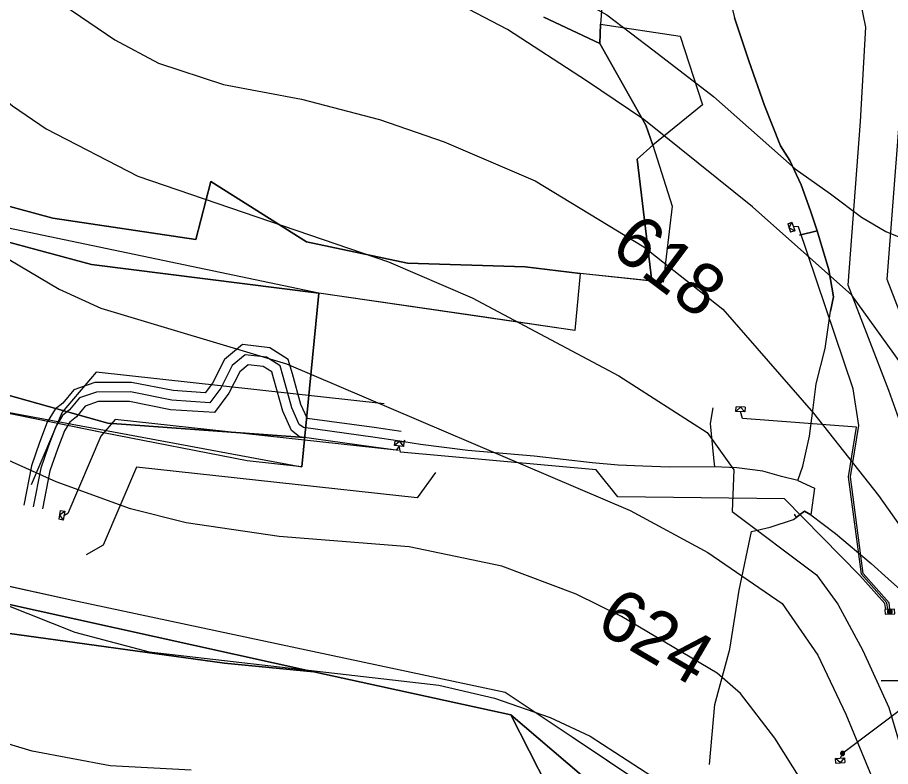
# Model space of a CAD drawing. Extents: x -709418 to -703832, y -1161719 to -1157826.
# Drawn here: x -707168.1 to -707032.1, y -1160311.5 to -1160194.8 of the extents above; entities that cross this region are included whole.
import ezdxf

# ---------------------------------------------------------------- set-up
doc = ezdxf.new("R2010")
doc.units = 0
for name, color, linetype in [('102_obvod PÚ', 7, 'Continuous'), ('106_zastavitelné plochy', 7, 'Continuous'), ('120_vrstevnice hlavní', 7, 'Continuous'), ('121_vrstevnice hlavní_popis', 7, 'Continuous'), ('122_vrstevnice základní', 7, 'Continuous'), ('204_zahrada_KN', 7, 'Continuous'), ('206_TTP_KN', 7, 'Continuous'), ('210_ostatní plocha_KN', 7, 'Continuous'), ('501_vodní tok', 7, 'Continuous'), ('708_el NN nadzemní a podzemní_ E.ON', 7, 'Continuous'), ('717_elektronická komunikace O2', 7, 'Continuous'), ('735_OP sítí TI', 7, 'Continuous')]:
    doc.layers.add(name, color=color, linetype=linetype)

# ---------------------------------------------------------------- blocks, each defined once
blk = doc.blocks.new('Elektro - Implicitní$0$NN4601')
for points in [[(0.63, 0), (0.62, 0.07), (0.61, 0.13), (0.6, 0.2), (0.57, 0.26), (0.54, 0.32), (0.51, 0.37), (0.47, 0.42), (0.42, 0.47), (0.37, 0.51), (0.31, 0.55), (0.25, 0.58), (0.19, 0.6), (0.13, 0.62), (0.06, 0.63), (0, 0.63), (-0.07, 0.63), (-0.13, 0.62), (-0.2, 0.6), (-0.26, 0.58), (-0.32, 0.55), (-0.37, 0.51), (-0.42, 0.47), (-0.47, 0.42), (-0.51, 0.37), (-0.55, 0.32), (-0.58, 0.26), (-0.6, 0.2), (-0.62, 0.13), (-0.63, 0.07), (-0.63, 0), (-0.63, -0.07), (-0.62, -0.13), (-0.6, -0.19), (-0.58, -0.26), (-0.55, -0.31), (-0.51, -0.37), (-0.47, -0.42), (-0.42, -0.47), (-0.37, -0.51), (-0.32, -0.54), (-0.26, -0.57), (-0.2, -0.6), (-0.13, -0.62), (-0.07, -0.63), (0, -0.63), (0.06, -0.63), (0.13, -0.62), (0.19, -0.6), (0.25, -0.57), (0.31, -0.54), (0.37, -0.51), (0.42, -0.47), (0.47, -0.42), (0.51, -0.37), (0.54, -0.31), (0.57, -0.26), (0.6, -0.19), (0.61, -0.13), (0.62, -0.07), (0.63, 0)], [(0.47, 0), (0.47, 0.05), (0.46, 0.1), (0.45, 0.15), (0.43, 0.19), (0.41, 0.24), (0.38, 0.28), (0.35, 0.32), (0.31, 0.35), (0.28, 0.38), (0.23, 0.41), (0.19, 0.43), (0.14, 0.45), (0.1, 0.46), (0.05, 0.47), (0, 0.47), (-0.05, 0.47), (-0.1, 0.46), (-0.15, 0.45), (-0.19, 0.43), (-0.24, 0.41), (-0.28, 0.38), (-0.32, 0.35), (-0.35, 0.32), (-0.38, 0.28), (-0.41, 0.24), (-0.43, 0.19), (-0.45, 0.15), (-0.46, 0.1), (-0.47, 0.05), (-0.47, 0), (-0.47, -0.05), (-0.46, -0.1), (-0.45, -0.15), (-0.43, -0.19), (-0.41, -0.24), (-0.38, -0.28), (-0.35, -0.32), (-0.32, -0.35), (-0.28, -0.38), (-0.24, -0.41), (-0.19, -0.43), (-0.15, -0.45), (-0.1, -0.46), (-0.05, -0.47), (0, -0.47), (0.05, -0.47), (0.1, -0.46), (0.14, -0.45), (0.19, -0.43), (0.23, -0.41), (0.28, -0.38), (0.31, -0.35), (0.35, -0.32), (0.38, -0.28), (0.41, -0.24), (0.43, -0.19), (0.45, -0.15), (0.46, -0.1), (0.47, -0.05), (0.47, 0)], [(0.31, 0), (0.31, 0.03), (0.31, 0.07), (0.3, 0.1), (0.29, 0.13), (0.27, 0.16), (0.25, 0.19), (0.23, 0.21), (0.21, 0.23), (0.18, 0.26), (0.15, 0.27), (0.13, 0.29), (0.09, 0.3), (0.06, 0.31), (0.03, 0.31), (0, 0.32), (-0.04, 0.31), (-0.07, 0.31), (-0.1, 0.3), (-0.13, 0.29), (-0.16, 0.27), (-0.19, 0.26), (-0.21, 0.23), (-0.24, 0.21), (-0.26, 0.19), (-0.28, 0.16), (-0.29, 0.13), (-0.3, 0.1), (-0.31, 0.07), (-0.32, 0.03), (-0.32, 0), (-0.32, -0.03), (-0.31, -0.06), (-0.3, -0.1), (-0.29, -0.13), (-0.28, -0.16), (-0.26, -0.18), (-0.24, -0.21), (-0.21, -0.23), (-0.19, -0.25), (-0.16, -0.27), (-0.13, -0.29), (-0.1, -0.3), (-0.07, -0.31), (-0.04, -0.31), (0, -0.31), (0.03, -0.31), (0.06, -0.31), (0.09, -0.3), (0.13, -0.29), (0.15, -0.27), (0.18, -0.25), (0.21, -0.23), (0.23, -0.21), (0.25, -0.18), (0.27, -0.16), (0.29, -0.13), (0.3, -0.1), (0.31, -0.06), (0.31, -0.03), (0.31, 0)], [(0.15, 0), (0.15, 0.02), (0.15, 0.03), (0.15, 0.05), (0.14, 0.06), (0.13, 0.08), (0.13, 0.09), (0.11, 0.11), (0.1, 0.12), (0.09, 0.13), (0.08, 0.14), (0.06, 0.14), (0.05, 0.15), (0.03, 0.15), (0.01, 0.16), (0, 0.16), (-0.02, 0.16), (-0.04, 0.15), (-0.05, 0.15), (-0.07, 0.14), (-0.08, 0.14), (-0.09, 0.13), (-0.11, 0.12), (-0.12, 0.11), (-0.13, 0.09), (-0.14, 0.08), (-0.15, 0.06), (-0.15, 0.05), (-0.16, 0.03), (-0.16, 0.02), (-0.16, 0), (-0.16, -0.02), (-0.16, -0.03), (-0.15, -0.05), (-0.15, -0.06), (-0.14, -0.08), (-0.13, -0.09), (-0.12, -0.1), (-0.11, -0.12), (-0.09, -0.13), (-0.08, -0.14), (-0.07, -0.14), (-0.05, -0.15), (-0.04, -0.15), (-0.02, -0.16), (0, -0.16), (0.01, -0.16), (0.03, -0.15), (0.05, -0.15), (0.06, -0.14), (0.08, -0.14), (0.09, -0.13), (0.1, -0.12), (0.11, -0.1), (0.13, -0.09), (0.13, -0.08), (0.14, -0.06), (0.15, -0.05), (0.15, -0.03), (0.15, -0.02), (0.15, 0)]]:
    blk.add_lwpolyline(points)
blk = doc.blocks.new('Elektro - Implicitní$0$NN6301')
for points in [[(0, -0.7), (-0.7, 0)], [(-0.7, -0.7), (-0.7, 0), (0.7, 0), (0.7, -0.7)], [(-0.7, -0.7), (0.7, -0.7)], [(0, -0.7), (0.7, 0)]]:
    blk.add_lwpolyline(points)
blk = doc.blocks.new('Elektro - Implicitní$0$NN6201')
for points in [[(0.75, 0), (-0.75, 0)], [(-0.75, 0), (-0.75, -0.75)], [(0.75, -0.75), (0.75, 0)], [(-0.75, -0.75), (0.75, -0.75)], [(0.37, -0.18), (-0.38, -0.18)], [(-0.38, -0.18), (-0.38, -0.56)], [(-0.38, -0.56), (0.37, -0.56)], [(0.32, -0.23), (-0.33, -0.23)], [(-0.33, -0.23), (-0.33, -0.51)], [(-0.33, -0.51), (0.32, -0.51)], [(0.27, -0.27), (-0.28, -0.27)], [(-0.28, -0.27), (-0.28, -0.46)], [(-0.28, -0.46), (0.27, -0.46)], [(0.23, -0.32), (-0.23, -0.32)], [(-0.23, -0.32), (-0.23, -0.42)], [(-0.23, -0.42), (0.23, -0.42)], [(-0.19, -0.37), (0.19, -0.37)], [(0.23, -0.42), (0.23, -0.32)], [(0.27, -0.46), (0.27, -0.27)], [(0.32, -0.51), (0.32, -0.23)], [(0.37, -0.56), (0.37, -0.18)]]:
    blk.add_lwpolyline(points)

msp = doc.modelspace()

# ---------------------------------------------------------------- linework, layer by layer
at = {"layer": '102_obvod PÚ'}
for points in [[(-707069.74, -1160077.73), (-707051.26, -1160126.04), (-707048.48, -1160146.16), (-707064.34, -1160162.06), (-707070.51, -1160163.59), (-707070.58, -1160162.59), (-707113.49, -1160155.37), (-707117.48, -1160184.48), (-707076.81, -1160189.76), (-707077.24, -1160195.83), (-707064.82, -1160197.68), (-707061.39, -1160208.39), (-707069.1, -1160214.67), (-707066.07, -1160224.17), (-707067.49, -1160236.02), (-707080.41, -1160234.66), (-707081.27, -1160243.51), (-707121.16, -1160237.73), (-707123.8, -1160264.78), (-707132.29, -1160263.85), (-707154.7, -1160259.5), (-707179.46, -1160254.43)], [(-707185.1, -1160279.91), (-707159.48, -1160285.54), (-707092.11, -1160299.89), (-707081.66, -1160306.81), (-707065.6, -1160317.58)]]:
    msp.add_lwpolyline(points, dxfattribs=at)
at = {"layer": '106_zastavitelné plochy'}
msp.add_lwpolyline([(-707218.12, -1160217.44), (-707231.07, -1160267.18), (-707185.1, -1160279.91), (-707179.46, -1160254.43), (-707123.8, -1160264.78), (-707121.16, -1160237.73), (-707218.12, -1160217.44)], dxfattribs=at)
at = {"layer": '120_vrstevnice hlavní'}
msp.add_lwpolyline([(-707200.36, -1160178.58), (-707183.6, -1160196.23), (-707168.85, -1160208.52), (-707163.64, -1160212.14), (-707149.32, -1160219.52), (-707110.26, -1160232.82), (-707097.25, -1160238.46), (-707074.39, -1160250.61), (-707060.65, -1160259.44), (-707056.47, -1160265.22), (-707056.72, -1160271.75), (-707043.58, -1160281.57), (-707040.29, -1160286.17), (-707036.39, -1160293.38), (-707032.35, -1160302.26), (-707030.28, -1160309.28)], dxfattribs=at)
at = {"layer": '122_vrstevnice základní'}
for points in [[(-707228.15, -1160106.11), (-707204.14, -1160119.57), (-707193.87, -1160126.8), (-707180.27, -1160138.95), (-707162.62, -1160151.24), (-707144.11, -1160162.96), (-707136.44, -1160167.15), (-707127.91, -1160170.92), (-707107.95, -1160177.57), (-707101.73, -1160180.17), (-707076.27, -1160194.35), (-707068.9, -1160199.99), (-707059.64, -1160207.08), (-707046.91, -1160218.36), (-707041.41, -1160222.26), (-707036.62, -1160225.88), (-707032.82, -1160228.1), (-707029, -1160229.65)], [(-707171.93, -1160185.32), (-707152.93, -1160198.25), (-707146.14, -1160201.87), (-707136.01, -1160205.2), (-707123.86, -1160207.51), (-707111.71, -1160210.69), (-707101.59, -1160214.16), (-707087.41, -1160220.24), (-707070.49, -1160230.51), (-707058.19, -1160240.2), (-707044.08, -1160256.43), (-707033.93, -1160269.23), (-707029.68, -1160275.28), (-707025.1, -1160281.33), (-707020.67, -1160286.06), (-707017.03, -1160287.77), (-707012.11, -1160288.36), (-707005.71, -1160288.09), (-707003.18, -1160285.96), (-707001.47, -1160282.49), (-707001.22, -1160276.33), (-707001.69, -1160264.81), (-706995.49, -1160261.9), (-706993, -1160250.04)], [(-707003.89, -1160225.22), (-707010.68, -1160228.43), (-707010.05, -1160249.05), (-707011.14, -1160255.7), (-707013.03, -1160259.68), (-707016.21, -1160261.14), (-707020.37, -1160260.41), (-707023.5, -1160258.2), (-707025.8, -1160255.17), (-707031.58, -1160247.14), (-707038.09, -1160238.03), (-707053.56, -1160224.29), (-707070.49, -1160210.69), (-707079.45, -1160204.62), (-707091.75, -1160196.66), (-707097.82, -1160193.48), (-707107.95, -1160190.01), (-707122.56, -1160186.39)], [(-707173.89, -1160229.82), (-707161.58, -1160237.08), (-707155.1, -1160240.06), (-707126.17, -1160248.73), (-707072.66, -1160271.59), (-707060.51, -1160278.1), (-707048.93, -1160286.05), (-707043.39, -1160294.11), (-707039.03, -1160303.32), (-707032.8, -1160318.33), (-707030.42, -1160326.35)], [(-707216.25, -1160247.81), (-707208.81, -1160257.2), (-707199.51, -1160265.66), (-707189.82, -1160273.32), (-707182.01, -1160279.11), (-707170, -1160286.2), (-707159.15, -1160290.54), (-707147.58, -1160293.57), (-707102.45, -1160298.78), (-707093.77, -1160300.81), (-707085.1, -1160303.84), (-707078.88, -1160306.74), (-707059.64, -1160319.18), (-707053.71, -1160325.83), (-707046.47, -1160335.67), (-707040.84, -1160347.05), (-707036.98, -1160356.57), (-707033.79, -1160366.42), (-707031, -1160381.41), (-707032.56, -1160386.71), (-707026.38, -1160395.27)], [(-707009.56, -1160420.55), (-707013.67, -1160417.17), (-707015.1, -1160412), (-707016.15, -1160403.5), (-707018.79, -1160390.33), (-707020.84, -1160381.99), (-707021.89, -1160373.85), (-707025.49, -1160344.4), (-707030.48, -1160344.5), (-707033.85, -1160335.48), (-707040, -1160323.09), (-707050.09, -1160307.03), (-707055.44, -1160300.08), (-707059.06, -1160296.9), (-707073.96, -1160288.08), (-707081.05, -1160284.6), (-707092.62, -1160280.27), (-707107.08, -1160277.23), (-707127.33, -1160275.64), (-707141.8, -1160273.47), (-707150.47, -1160271.3), (-707162.05, -1160267.1), (-707173.62, -1160261.9), (-707178.97, -1160258.86)], [(-707141.04, -1160312.04), (-707153.66, -1160311.36), (-707165.81, -1160309.05), (-707186.06, -1160302.98), (-707194.16, -1160299.79), (-707203.12, -1160294.44), (-707212.82, -1160287.21)]]:
    msp.add_lwpolyline(points, dxfattribs=at)
at = {"layer": '204_zahrada_KN'}
for p, q in [((-707211.57, -1160218.56), (-707156.55, -1160233.24)), ((-707156.55, -1160233.24), (-707121.16, -1160237.73)), ((-707121.16, -1160237.73), (-707123.37, -1160260.19)), ((-707154.02, -1160257.98), (-707199.62, -1160245.21)), ((-707123.37, -1160260.19), (-707154.02, -1160257.98))]:
    msp.add_line(p, q, dxfattribs=at)
at = {"layer": '206_TTP_KN'}
for p, q in [((-707086.08, -1160194.71), (-707077.34, -1160198.84)), ((-707077.34, -1160198.84), (-707070.21, -1160211.54)), ((-707070.21, -1160211.54), (-707069.1, -1160214.67)), ((-707069.1, -1160214.67), (-707071.55, -1160216.87)), ((-707071.55, -1160216.87), (-707069.1, -1160214.67)), ((-707069.1, -1160214.67), (-707066.07, -1160224.17)), ((-707071.55, -1160216.87), (-707069.28, -1160235.83)), ((-707069.28, -1160235.83), (-707071.55, -1160216.87)), ((-707137.96, -1160220.33), (-707140.3, -1160229.38)), ((-707123.08, -1160229.75), (-707137.96, -1160220.33)), ((-707162.56, -1160226.02), (-707178.69, -1160221.67)), ((-707066.07, -1160224.17), (-707067.49, -1160236.02)), ((-707140.3, -1160229.38), (-707162.56, -1160226.02)), ((-707107.31, -1160233.07), (-707123.08, -1160229.75)), ((-707089.01, -1160233.6), (-707107.31, -1160233.07)), ((-707080.41, -1160234.66), (-707089.01, -1160233.6)), ((-707069.28, -1160235.83), (-707080.41, -1160234.66)), ((-707067.49, -1160236.02), (-707069.28, -1160235.83)), ((-707181.48, -1160289.09), (-707135.81, -1160295.36)), ((-707135.81, -1160295.36), (-707121.9, -1160296.72)), ((-707121.9, -1160296.72), (-707091.23, -1160303.38)), ((-707091.23, -1160303.38), (-707083.56, -1160318.4)), ((-707083.56, -1160318.4), (-707091.23, -1160303.38)), ((-707091.23, -1160303.38), (-707068.93, -1160322.43))]:
    msp.add_line(p, q, dxfattribs=at)
at = {"layer": '210_ostatní plocha_KN'}
for p, q in [((-707076.81, -1160189.76), (-707077.24, -1160195.83)), ((-707077.34, -1160198.84), (-707086.08, -1160194.71)), ((-707077.24, -1160195.83), (-707077.34, -1160198.84)), ((-707077.34, -1160198.84), (-707077.24, -1160195.83)), ((-707077.24, -1160195.83), (-707064.82, -1160197.68)), ((-707064.82, -1160197.68), (-707061.39, -1160208.39)), ((-707070.21, -1160211.54), (-707077.34, -1160198.84)), ((-707061.39, -1160208.39), (-707069.1, -1160214.67)), ((-707069.1, -1160214.67), (-707070.21, -1160211.54)), ((-707156.55, -1160233.24), (-707211.57, -1160218.56)), ((-707140.3, -1160229.38), (-707137.96, -1160220.33)), ((-707137.96, -1160220.33), (-707123.08, -1160229.75)), ((-707178.69, -1160221.67), (-707162.56, -1160226.02)), ((-707162.56, -1160226.02), (-707140.3, -1160229.38)), ((-707123.08, -1160229.75), (-707107.31, -1160233.07)), ((-707121.16, -1160237.73), (-707156.55, -1160233.24)), ((-707107.31, -1160233.07), (-707089.01, -1160233.6)), ((-707089.01, -1160233.6), (-707080.41, -1160234.66)), ((-707080.41, -1160234.66), (-707081.27, -1160243.51)), ((-707095.62, -1160241.43), (-707121.16, -1160237.73)), ((-707083.04, -1160243.26), (-707095.62, -1160241.43)), ((-707081.27, -1160243.51), (-707083.04, -1160243.26)), ((-707199.62, -1160245.21), (-707154.02, -1160257.98)), ((-707154.7, -1160259.5), (-707179.46, -1160254.43)), ((-707154.02, -1160257.98), (-707123.37, -1160260.19)), ((-707132.29, -1160263.85), (-707154.7, -1160259.5)), ((-707123.37, -1160260.19), (-707123.8, -1160264.78)), ((-707123.8, -1160264.78), (-707132.29, -1160263.85)), ((-707121.9, -1160296.72), (-707204.36, -1160278.47)), ((-707204.36, -1160278.47), (-707121.9, -1160296.72)), ((-707185.1, -1160279.91), (-707159.48, -1160285.54)), ((-707159.48, -1160285.54), (-707092.11, -1160299.89)), ((-707135.81, -1160295.36), (-707181.48, -1160289.09)), ((-707121.9, -1160296.72), (-707135.81, -1160295.36)), ((-707091.23, -1160303.38), (-707121.9, -1160296.72)), ((-707092.11, -1160299.89), (-707081.66, -1160306.81)), ((-707068.93, -1160322.43), (-707091.23, -1160303.38)), ((-707081.66, -1160306.81), (-707065.6, -1160317.58))]:
    msp.add_line(p, q, dxfattribs=at)
at = {"layer": '501_vodní tok'}
msp.add_lwpolyline([(-707026.72, -1160250.76), (-707032.59, -1160235.58), (-707030.74, -1160211.37)], dxfattribs=at)
at = {"layer": '708_el NN nadzemní a podzemní_ E.ON'}
for points in [[(-707032.19, -1160286.96), (-707032.31, -1160285.93), (-707036.33, -1160281.38), (-707038.31, -1160266.33), (-707037.02, -1160258.31), (-707037.91, -1160252.62), (-707046.42, -1160227.37), (-707047.21, -1160227.35)], [(-707032.49, -1160286.97), (-707032.67, -1160285.96), (-707036.62, -1160281.51), (-707038.61, -1160266.33), (-707037.37, -1160258.59), (-707055.15, -1160257.25), (-707055.46, -1160256.16)], [(-707108.64, -1160261.54), (-707109.1, -1160262.18), (-707152.89, -1160257.4), (-707155.09, -1160259.99), (-707160.25, -1160272.04), (-707160.85, -1160272.38)], [(-707032.79, -1160286.98), (-707032.97, -1160286.08), (-707036.84, -1160281.71), (-707048.58, -1160269.74), (-707074.58, -1160269.45), (-707077.93, -1160265.24), (-707108.43, -1160262.47), (-707108.64, -1160261.54)], [(-707024.88, -1160298.37), (-707039.54, -1160309.41), (-707039.94, -1160310.16)]]:
    msp.add_lwpolyline(points, dxfattribs=at)
at = {"layer": '717_elektronická komunikace O2'}
for points in [[(-707058.23, -1160182.17), (-707057.87, -1160186.77), (-707057.48, -1160190.34), (-707056.39, -1160194.84), (-707054.15, -1160201.55), (-707051.69, -1160208.47), (-707049.19, -1160214.75), (-707047.78, -1160217.08), (-707045.99, -1160220.87), (-707044.53, -1160224.88), (-707043.49, -1160228.01)], [(-707044.13, -1160255.59), (-707043.65, -1160251.82), (-707042.23, -1160246.32), (-707041.45, -1160240.54), (-707040.96, -1160238.27), (-707041.7, -1160234.06), (-707043.49, -1160228.01), (-707044.53, -1160224.88), (-707045.99, -1160220.87), (-707047.78, -1160217.08), (-707049.19, -1160214.75), (-707051.69, -1160208.47), (-707054.15, -1160201.55), (-707056.39, -1160194.84)], [(-707043.49, -1160228.01), (-707046.26, -1160228.67)], [(-707046.26, -1160228.67), (-707043.49, -1160228.01)], [(-707043.49, -1160228.01), (-707041.7, -1160234.06), (-707040.96, -1160238.27), (-707041.45, -1160240.54)], [(-707046.52, -1160266.9), (-707045.76, -1160264.69), (-707044.7, -1160259.99), (-707044.13, -1160255.59), (-707043.65, -1160251.82), (-707042.23, -1160246.32), (-707041.45, -1160240.54)], [(-707108.52, -1160260.76), (-707112.75, -1160260.15), (-707123.53, -1160258.66), (-707124.18, -1160258.16), (-707125.36, -1160255.59), (-707126.71, -1160250.71), (-707127.18, -1160249.02), (-707129.27, -1160247.67), (-707132.59, -1160247.3), (-707134.66, -1160249), (-707136.43, -1160252.52), (-707138.12, -1160254.78), (-707144.03, -1160254.38), (-707150.46, -1160253.11), (-707155.79, -1160253.12), (-707158.44, -1160254.04), (-707159.97, -1160255.9), (-707161.06, -1160256.79), (-707162.13, -1160258.49), (-707163.26, -1160261.49), (-707164.47, -1160264.98), (-707165.65, -1160271.01)], [(-707158.44, -1160254.04), (-707159.97, -1160255.9), (-707161.06, -1160256.79), (-707162.13, -1160258.49), (-707163.26, -1160261.49), (-707164.47, -1160264.98), (-707165.65, -1160271.01)], [(-707059.75, -1160255.57), (-707060.16, -1160258.03), (-707059.64, -1160263.38), (-707059.51, -1160264.77)], [(-707059.75, -1160255.57), (-707060.16, -1160258.03), (-707059.64, -1160263.38), (-707059.51, -1160264.77)], [(-707070.67, -1160264.66), (-707074.52, -1160264.51), (-707078.53, -1160264.14), (-707087.61, -1160263.12), (-707097.9, -1160262.23), (-707105.3, -1160261.31), (-707107.88, -1160260.9), (-707108.52, -1160260.76), (-707112.75, -1160260.15), (-707123.53, -1160258.66)], [(-707107.88, -1160260.9), (-707108.52, -1160260.76)], [(-707107.88, -1160260.9), (-707107.69, -1160260.63)], [(-707059.51, -1160264.77), (-707066.53, -1160264.83), (-707070.67, -1160264.66), (-707074.52, -1160264.51), (-707078.53, -1160264.14), (-707087.61, -1160263.12), (-707097.9, -1160262.23), (-707105.3, -1160261.31), (-707107.88, -1160260.9)], [(-707046.52, -1160266.9), (-707049.08, -1160266.26), (-707051.95, -1160265.45), (-707056.04, -1160264.91), (-707059.51, -1160264.77)], [(-707046.52, -1160266.9), (-707043.92, -1160268.09), (-707044.49, -1160272.25)], [(-707046.52, -1160266.9), (-707043.92, -1160268.09), (-707044.49, -1160272.25)], [(-707053.72, -1160274.82), (-707050.83, -1160274.19), (-707047.17, -1160272.97), (-707046.75, -1160272.66), (-707045.48, -1160271.7), (-707044.49, -1160272.25), (-707040.62, -1160275.15), (-707035.09, -1160279.83)], [(-707044.49, -1160272.25), (-707045.48, -1160271.7), (-707046.75, -1160272.66)], [(-707060.28, -1160311.14), (-707059.46, -1160301.77), (-707057.13, -1160293.16), (-707055.66, -1160283.99), (-707053.72, -1160274.82), (-707050.83, -1160274.19), (-707047.17, -1160272.97), (-707046.75, -1160272.66)], [(-707047.11, -1160272.17), (-707046.75, -1160272.66)], [(-707044.49, -1160272.25), (-707040.62, -1160275.15), (-707035.09, -1160279.83), (-707032.42, -1160282.22), (-707029.09, -1160285.23), (-707026.16, -1160288.67), (-707025.66, -1160289.26)], [(-707035.09, -1160279.83), (-707032.42, -1160282.22), (-707029.09, -1160285.23), (-707026.16, -1160288.67)], [(-707033.54, -1160298.1), (-707030.74, -1160298.05), (-707029.86, -1160293.62), (-707027.68, -1160290.74), (-707025.66, -1160289.26)], [(-707030.74, -1160298.05), (-707033.54, -1160298.1)], [(-707060.28, -1160311.14), (-707059.46, -1160301.77)]]:
    msp.add_lwpolyline(points, dxfattribs=at)
at = {"layer": '735_OP sítí TI'}
for points in [[(-707028.42, -1160263.76), (-707032.34, -1160252.86), (-707038.67, -1160236.48), (-707036.73, -1160210.98), (-707035.94, -1160196.28), (-707037.51, -1160188.41), (-707039.52, -1160183.38), (-707046.09, -1160177.55), (-707050.83, -1160172.26), (-707051.27, -1160163.17), (-707053.89, -1160151.56), (-707061.12, -1160118.18), (-707068.72, -1160090.57), (-707080.37, -1160060.14), (-707091.81, -1160036.5), (-707100.83, -1160006.45), (-707102.7, -1159989.51), (-707111.95, -1159970.41), (-707117.1, -1159942.88), (-707120.68, -1159925.89), (-707123.76, -1159912.78), (-707125.74, -1159895.33)], [(-707108.31, -1160259.28), (-707112.54, -1160258.66), (-707122.93, -1160257.23), (-707122.97, -1160257.2), (-707123.95, -1160255.07), (-707125.26, -1160250.31), (-707125.89, -1160248.07), (-707128.75, -1160246.22), (-707133.05, -1160245.74), (-707135.86, -1160248.04), (-707137.71, -1160251.73), (-707138.83, -1160253.23), (-707143.83, -1160252.89), (-707150.31, -1160251.61), (-707156.04, -1160251.62), (-707159.33, -1160252.76), (-707161.03, -1160254.83), (-707162.2, -1160255.78), (-707163.48, -1160257.82), (-707164.67, -1160260.98), (-707165.92, -1160264.59), (-707167.12, -1160270.72)], [(-707108.73, -1160262.24), (-707112.96, -1160261.64), (-707124.13, -1160260.09), (-707125.39, -1160259.12), (-707126.77, -1160256.11), (-707128.16, -1160251.11), (-707128.47, -1160249.97), (-707129.79, -1160249.12), (-707132.13, -1160248.86), (-707133.46, -1160249.96), (-707135.15, -1160253.31), (-707137.41, -1160256.33), (-707144.23, -1160255.87), (-707150.61, -1160254.61), (-707155.54, -1160254.62), (-707157.55, -1160255.32), (-707158.91, -1160256.97), (-707159.92, -1160257.8), (-707160.78, -1160259.16), (-707161.85, -1160262), (-707163.02, -1160265.37), (-707164.18, -1160271.3)], [(-707110.96, -1160254.94), (-707155.82, -1160250.04), (-707161.11, -1160256.26), (-707165.96, -1160267.6)], [(-707102.96, -1160265.63), (-707105.8, -1160269.58), (-707149.54, -1160264.81), (-707154.74, -1160276.97), (-707157.4, -1160278.47)]]:
    msp.add_lwpolyline(points, dxfattribs=at)

# ---------------------------------------------------------------- block references
at = {"layer": '708_el NN nadzemní a podzemní_ E.ON'}
for name, p, rotation in [('Elektro - Implicitní$0$NN6301', (-707047.21, -1160227.35), -71.8340278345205), ('Elektro - Implicitní$0$NN6301', (-707055.46, -1160256.16), 177.91205286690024), ('Elektro - Implicitní$0$NN6301', (-707108.64, -1160261.54), 174.51063323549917), ('Elektro - Implicitní$0$NN6301', (-707160.85, -1160272.38), -100.41838885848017), ('Elektro - Implicitní$0$NN6201', (-707032.19, -1160286.96), 1.77533616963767), ('Elektro - Implicitní$0$NN6301', (-707039.94, -1160310.16), 4.66677227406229)]:
    msp.add_blockref(name, p, dxfattribs=dict(at, rotation=rotation))
at = {"layer": '708_el NN nadzemní a podzemní_ E.ON', "xscale": 0.5, "yscale": 0.5, "rotation": -175.79352495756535}
msp.add_blockref('Elektro - Implicitní$0$NN4601', (-707039.54, -1160309.41), dxfattribs=at)

# ---------------------------------------------------------------- texts
at = {"layer": '121_vrstevnice hlavní_popis'}
for s, rotation, p in [('618', 323.116, (-707076.01, -1160231.22)), ('624', 329.658, (-707078.29, -1160290.06))]:
    msp.add_text(s, height=8, rotation=rotation, dxfattribs=at).set_placement(p)

doc.saveas('drawing.dxf')
